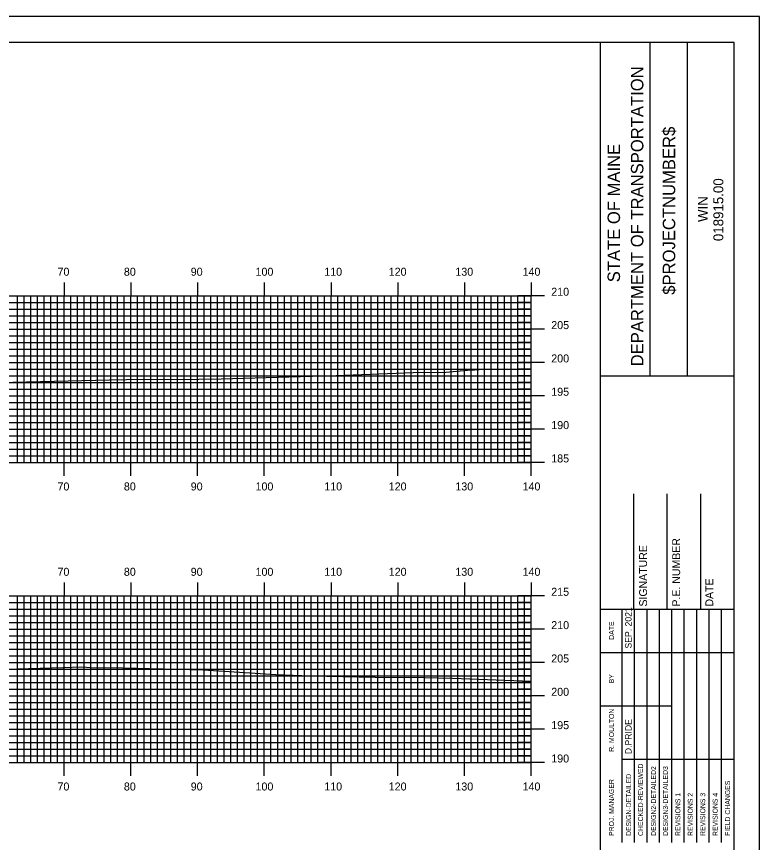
# Model space of a CAD drawing. Extents: x 1821998 to 1822342, y 442591 to 442811.
# Drawn here: x 1822227.1 to 1822338.5, y 442686.7 to 442810.5 of the extents above; entities that cross this region are included whole.
import ezdxf

# ---------------------------------------------------------------- set-up
doc = ezdxf.new("R2010")
doc.units = 0
for name, color, linetype in [('BORDER', 7, 'Continuous'), ('H_V ANNOTATION', 7, 'Continuous'), ('MAJOR', 7, 'Continuous'), ('MINOR', 7, 'Continuous'), ('PLOT BOUNDARY', 7, 'Continuous'), ('S_Roadway_Centerline', 7, 'Continuous')]:
    doc.layers.add(name, color=color, linetype=linetype)

msp = doc.modelspace()

# ---------------------------------------------------------------- linework, layer by layer
at = {"layer": 'BORDER'}
for p, q in [((1822314.66, 442596.67), (1822314.66, 442806.67)), ((1822322.11, 442756.66), (1822322.11, 442806.66)), ((1822327.7, 442756.66), (1822327.7, 442806.66)), ((1822314.66, 442756.65), (1822334.66, 442756.65)), ((1822319.66, 442721.67), (1822319.66, 442738.97)), ((1822324.66, 442721.67), (1822324.66, 442738.97)), ((1822329.66, 442721.67), (1822329.66, 442738.97)), ((1822314.66, 442721.67), (1822334.66, 442721.67))]:
    msp.add_line(p, q, dxfattribs=at)
msp.add_lwpolyline([(1822014.66, 442596.67), (1822334.66, 442596.67), (1822334.66, 442806.67), (1822014.66, 442806.67)], close=True, dxfattribs=at)
for points in [[(1822317.89, 442715.17), (1822317.89, 442721.67)], [(1822319.75, 442686.68), (1822319.75, 442721.67)], [(1822321.61, 442721.67), (1822321.61, 442686.68)], [(1822323.48, 442686.68), (1822323.48, 442721.67)], [(1822325.34, 442686.68), (1822325.34, 442721.67)], [(1822327.2, 442686.68), (1822327.2, 442721.67)], [(1822329.07, 442686.68), (1822329.07, 442721.67)], [(1822330.93, 442686.68), (1822330.93, 442721.67)], [(1822332.79, 442686.68), (1822332.79, 442721.67)], [(1822317.89, 442686.68), (1822317.89, 442720.26)], [(1822314.66, 442715.17), (1822334.66, 442715.17)], [(1822314.66, 442707.17), (1822317.89, 442707.17)], [(1822317.89, 442707.17), (1822325.34, 442707.17)], [(1822317.89, 442699.17), (1822334.66, 442699.17)]]:
    msp.add_lwpolyline(points, dxfattribs=at)
at = {"layer": 'MAJOR'}
for p, q in [((1822234.26, 442770.67), (1822234.26, 442768.67)), ((1822244.26, 442770.67), (1822244.26, 442768.67)), ((1822254.26, 442770.67), (1822254.26, 442768.67)), ((1822264.26, 442770.67), (1822264.26, 442768.67)), ((1822274.26, 442770.67), (1822274.26, 442768.67)), ((1822284.26, 442770.67), (1822284.26, 442768.67)), ((1822294.26, 442770.67), (1822294.26, 442768.67)), ((1822304.26, 442770.67), (1822304.26, 442768.67)), ((1822024.26, 442768.67), (1822304.26, 442768.67)), ((1822024.26, 442768.67), (1822304.26, 442768.67)), ((1822234.26, 442743.67), (1822234.26, 442768.67)), ((1822244.26, 442743.67), (1822244.26, 442768.67)), ((1822254.26, 442743.67), (1822254.26, 442768.67)), ((1822264.26, 442743.67), (1822264.26, 442768.67)), ((1822274.26, 442743.67), (1822274.26, 442768.67)), ((1822284.26, 442743.67), (1822284.26, 442768.67)), ((1822294.26, 442743.67), (1822294.26, 442768.67)), ((1822306.26, 442768.67), (1822302.25, 442768.67)), ((1822304.26, 442743.67), (1822304.26, 442768.67)), ((1822304.26, 442743.67), (1822304.26, 442768.67)), ((1822024.26, 442763.67), (1822304.26, 442763.67)), ((1822306.26, 442763.67), (1822302.25, 442763.67)), ((1822024.26, 442758.67), (1822304.26, 442758.67)), ((1822306.26, 442758.67), (1822302.25, 442758.67)), ((1822024.26, 442753.67), (1822304.26, 442753.67)), ((1822306.26, 442753.67), (1822302.25, 442753.67)), ((1822024.26, 442748.67), (1822304.26, 442748.67)), ((1822306.26, 442748.67), (1822302.25, 442748.67)), ((1822024.26, 442743.67), (1822304.26, 442743.67)), ((1822024.26, 442743.67), (1822304.26, 442743.67)), ((1822234.26, 442741.66), (1822234.26, 442743.67)), ((1822244.26, 442741.66), (1822244.26, 442743.67)), ((1822254.26, 442741.66), (1822254.26, 442743.67)), ((1822264.26, 442741.66), (1822264.26, 442743.67)), ((1822274.26, 442741.66), (1822274.26, 442743.67)), ((1822284.26, 442741.66), (1822284.26, 442743.67)), ((1822294.26, 442741.66), (1822294.26, 442743.67)), ((1822306.26, 442743.67), (1822302.25, 442743.67)), ((1822304.26, 442741.66), (1822304.26, 442743.67)), ((1822234.26, 442725.67), (1822234.26, 442723.67)), ((1822244.26, 442725.67), (1822244.26, 442723.67)), ((1822254.26, 442725.67), (1822254.26, 442723.67)), ((1822264.26, 442725.67), (1822264.26, 442723.67)), ((1822274.26, 442725.67), (1822274.26, 442723.67)), ((1822284.26, 442725.67), (1822284.26, 442723.67)), ((1822294.26, 442725.67), (1822294.26, 442723.67)), ((1822304.26, 442725.67), (1822304.26, 442723.67)), ((1822024.26, 442723.67), (1822304.26, 442723.67)), ((1822024.26, 442723.67), (1822304.26, 442723.67)), ((1822234.26, 442698.67), (1822234.26, 442723.67)), ((1822244.26, 442698.67), (1822244.26, 442723.67)), ((1822254.26, 442698.67), (1822254.26, 442723.67)), ((1822264.26, 442698.67), (1822264.26, 442723.67)), ((1822274.26, 442698.67), (1822274.26, 442723.67)), ((1822284.26, 442698.67), (1822284.26, 442723.67)), ((1822294.26, 442698.67), (1822294.26, 442723.67)), ((1822306.26, 442723.67), (1822302.25, 442723.67)), ((1822304.26, 442698.67), (1822304.26, 442723.67)), ((1822304.26, 442698.67), (1822304.26, 442723.67)), ((1822024.26, 442718.67), (1822304.26, 442718.67)), ((1822306.26, 442718.67), (1822302.25, 442718.67)), ((1822024.26, 442713.67), (1822304.26, 442713.67)), ((1822306.26, 442713.67), (1822302.25, 442713.67)), ((1822024.26, 442708.67), (1822304.26, 442708.67)), ((1822306.26, 442708.67), (1822302.25, 442708.67)), ((1822024.26, 442703.67), (1822304.26, 442703.67)), ((1822306.26, 442703.67), (1822302.25, 442703.67)), ((1822024.26, 442698.67), (1822304.26, 442698.67)), ((1822024.26, 442698.67), (1822304.26, 442698.67)), ((1822234.26, 442696.66), (1822234.26, 442698.67)), ((1822244.26, 442696.66), (1822244.26, 442698.67)), ((1822254.26, 442696.66), (1822254.26, 442698.67)), ((1822264.26, 442696.66), (1822264.26, 442698.67)), ((1822274.26, 442696.66), (1822274.26, 442698.67)), ((1822284.26, 442696.66), (1822284.26, 442698.67)), ((1822294.26, 442696.66), (1822294.26, 442698.67)), ((1822306.26, 442698.67), (1822302.25, 442698.67)), ((1822304.26, 442696.66), (1822304.26, 442698.67))]:
    msp.add_line(p, q, dxfattribs=at)
at = {"layer": 'MINOR'}
for p, q in [((1822227.26, 442743.67), (1822227.26, 442768.67)), ((1822228.26, 442743.67), (1822228.26, 442768.67)), ((1822229.26, 442743.67), (1822229.26, 442768.67)), ((1822230.26, 442743.67), (1822230.26, 442768.67)), ((1822231.26, 442743.67), (1822231.26, 442768.67)), ((1822232.26, 442743.67), (1822232.26, 442768.67)), ((1822233.26, 442743.67), (1822233.26, 442768.67)), ((1822235.26, 442743.67), (1822235.26, 442768.67)), ((1822236.26, 442743.67), (1822236.26, 442768.67)), ((1822237.26, 442743.67), (1822237.26, 442768.67)), ((1822238.26, 442743.67), (1822238.26, 442768.67)), ((1822239.26, 442743.67), (1822239.26, 442768.67)), ((1822240.26, 442743.67), (1822240.26, 442768.67)), ((1822241.26, 442743.67), (1822241.26, 442768.67)), ((1822242.26, 442743.67), (1822242.26, 442768.67)), ((1822243.26, 442743.67), (1822243.26, 442768.67)), ((1822245.26, 442743.67), (1822245.26, 442768.67)), ((1822246.26, 442743.67), (1822246.26, 442768.67)), ((1822247.26, 442743.67), (1822247.26, 442768.67)), ((1822248.26, 442743.67), (1822248.26, 442768.67)), ((1822249.26, 442743.67), (1822249.26, 442768.67)), ((1822250.26, 442743.67), (1822250.26, 442768.67)), ((1822251.26, 442743.67), (1822251.26, 442768.67)), ((1822252.26, 442743.67), (1822252.26, 442768.67)), ((1822253.26, 442743.67), (1822253.26, 442768.67)), ((1822255.26, 442743.67), (1822255.26, 442768.67)), ((1822256.26, 442743.67), (1822256.26, 442768.67)), ((1822257.26, 442743.67), (1822257.26, 442768.67)), ((1822258.26, 442743.67), (1822258.26, 442768.67)), ((1822259.26, 442743.67), (1822259.26, 442768.67)), ((1822260.26, 442743.67), (1822260.26, 442768.67)), ((1822261.26, 442743.67), (1822261.26, 442768.67)), ((1822262.26, 442743.67), (1822262.26, 442768.67)), ((1822263.26, 442743.67), (1822263.26, 442768.67)), ((1822265.26, 442743.67), (1822265.26, 442768.67)), ((1822266.26, 442743.67), (1822266.26, 442768.67)), ((1822267.26, 442743.67), (1822267.26, 442768.67)), ((1822268.26, 442743.67), (1822268.26, 442768.67)), ((1822269.26, 442743.67), (1822269.26, 442768.67)), ((1822270.26, 442743.67), (1822270.26, 442768.67)), ((1822271.26, 442743.67), (1822271.26, 442768.67)), ((1822272.26, 442743.67), (1822272.26, 442768.67)), ((1822273.26, 442743.67), (1822273.26, 442768.67)), ((1822275.26, 442743.67), (1822275.26, 442768.67)), ((1822276.26, 442743.67), (1822276.26, 442768.67)), ((1822277.26, 442743.67), (1822277.26, 442768.67)), ((1822278.26, 442743.67), (1822278.26, 442768.67)), ((1822279.26, 442743.67), (1822279.26, 442768.67)), ((1822280.26, 442743.67), (1822280.26, 442768.67)), ((1822281.26, 442743.67), (1822281.26, 442768.67)), ((1822282.26, 442743.67), (1822282.26, 442768.67)), ((1822283.26, 442743.67), (1822283.26, 442768.67)), ((1822285.26, 442743.67), (1822285.26, 442768.67)), ((1822286.26, 442743.67), (1822286.26, 442768.67)), ((1822287.26, 442743.67), (1822287.26, 442768.67)), ((1822288.26, 442743.67), (1822288.26, 442768.67)), ((1822289.26, 442743.67), (1822289.26, 442768.67)), ((1822290.26, 442743.67), (1822290.26, 442768.67)), ((1822291.26, 442743.67), (1822291.26, 442768.67)), ((1822292.26, 442743.67), (1822292.26, 442768.67)), ((1822293.26, 442743.67), (1822293.26, 442768.67)), ((1822295.26, 442743.67), (1822295.26, 442768.67)), ((1822296.26, 442743.67), (1822296.26, 442768.67)), ((1822297.26, 442743.67), (1822297.26, 442768.67)), ((1822298.26, 442743.67), (1822298.26, 442768.67)), ((1822299.26, 442743.67), (1822299.26, 442768.67)), ((1822300.26, 442743.67), (1822300.26, 442768.67)), ((1822301.26, 442743.67), (1822301.26, 442768.67)), ((1822302.26, 442743.67), (1822302.26, 442768.67)), ((1822303.26, 442743.67), (1822303.26, 442768.67)), ((1822024.26, 442767.67), (1822304.26, 442767.67)), ((1822304.26, 442767.67), (1822302.25, 442767.67)), ((1822024.26, 442766.67), (1822304.26, 442766.67)), ((1822304.26, 442766.67), (1822302.25, 442766.67)), ((1822024.26, 442765.67), (1822304.26, 442765.67)), ((1822304.26, 442765.67), (1822302.25, 442765.67)), ((1822024.26, 442764.67), (1822304.26, 442764.67)), ((1822304.26, 442764.67), (1822302.25, 442764.67)), ((1822024.26, 442762.67), (1822304.26, 442762.67)), ((1822304.26, 442762.67), (1822302.25, 442762.67)), ((1822024.26, 442761.67), (1822304.26, 442761.67)), ((1822304.26, 442761.67), (1822302.25, 442761.67)), ((1822024.26, 442760.67), (1822304.26, 442760.67)), ((1822304.26, 442760.67), (1822302.25, 442760.67)), ((1822024.26, 442759.67), (1822304.26, 442759.67)), ((1822304.26, 442759.67), (1822302.25, 442759.67)), ((1822024.26, 442757.67), (1822304.26, 442757.67)), ((1822304.26, 442757.67), (1822302.25, 442757.67)), ((1822024.26, 442756.67), (1822304.26, 442756.67)), ((1822304.26, 442756.67), (1822302.25, 442756.67)), ((1822024.26, 442755.67), (1822304.26, 442755.67)), ((1822304.26, 442755.67), (1822302.25, 442755.67)), ((1822024.26, 442754.67), (1822304.26, 442754.67)), ((1822304.26, 442754.67), (1822302.25, 442754.67)), ((1822024.26, 442752.67), (1822304.26, 442752.67)), ((1822304.26, 442752.67), (1822302.25, 442752.67)), ((1822024.26, 442751.67), (1822304.26, 442751.67)), ((1822304.26, 442751.67), (1822302.25, 442751.67)), ((1822024.26, 442750.67), (1822304.26, 442750.67)), ((1822304.26, 442750.67), (1822302.25, 442750.67)), ((1822024.26, 442749.67), (1822304.26, 442749.67)), ((1822304.26, 442749.67), (1822302.25, 442749.67)), ((1822024.26, 442747.67), (1822304.26, 442747.67)), ((1822304.26, 442747.67), (1822302.25, 442747.67)), ((1822024.26, 442746.67), (1822304.26, 442746.67)), ((1822304.26, 442746.67), (1822302.25, 442746.67)), ((1822024.26, 442745.67), (1822304.26, 442745.67)), ((1822304.26, 442745.67), (1822302.25, 442745.67)), ((1822024.26, 442744.67), (1822304.26, 442744.67)), ((1822304.26, 442744.67), (1822302.25, 442744.67)), ((1822227.26, 442698.67), (1822227.26, 442723.67)), ((1822228.26, 442698.67), (1822228.26, 442723.67)), ((1822229.26, 442698.67), (1822229.26, 442723.67)), ((1822230.26, 442698.67), (1822230.26, 442723.67)), ((1822231.26, 442698.67), (1822231.26, 442723.67)), ((1822232.26, 442698.67), (1822232.26, 442723.67)), ((1822233.26, 442698.67), (1822233.26, 442723.67)), ((1822235.26, 442698.67), (1822235.26, 442723.67)), ((1822236.26, 442698.67), (1822236.26, 442723.67)), ((1822237.26, 442698.67), (1822237.26, 442723.67)), ((1822238.26, 442698.67), (1822238.26, 442723.67)), ((1822239.26, 442698.67), (1822239.26, 442723.67)), ((1822240.26, 442698.67), (1822240.26, 442723.67)), ((1822241.26, 442698.67), (1822241.26, 442723.67)), ((1822242.26, 442698.67), (1822242.26, 442723.67)), ((1822243.26, 442698.67), (1822243.26, 442723.67)), ((1822245.26, 442698.67), (1822245.26, 442723.67)), ((1822246.26, 442698.67), (1822246.26, 442723.67)), ((1822247.26, 442698.67), (1822247.26, 442723.67)), ((1822248.26, 442698.67), (1822248.26, 442723.67)), ((1822249.26, 442698.67), (1822249.26, 442723.67)), ((1822250.26, 442698.67), (1822250.26, 442723.67)), ((1822251.26, 442698.67), (1822251.26, 442723.67)), ((1822252.26, 442698.67), (1822252.26, 442723.67)), ((1822253.26, 442698.67), (1822253.26, 442723.67)), ((1822255.26, 442698.67), (1822255.26, 442723.67)), ((1822256.26, 442698.67), (1822256.26, 442723.67)), ((1822257.26, 442698.67), (1822257.26, 442723.67)), ((1822258.26, 442698.67), (1822258.26, 442723.67)), ((1822259.26, 442698.67), (1822259.26, 442723.67)), ((1822260.26, 442698.67), (1822260.26, 442723.67)), ((1822261.26, 442698.67), (1822261.26, 442723.67)), ((1822262.26, 442698.67), (1822262.26, 442723.67)), ((1822263.26, 442698.67), (1822263.26, 442723.67)), ((1822265.26, 442698.67), (1822265.26, 442723.67)), ((1822266.26, 442698.67), (1822266.26, 442723.67)), ((1822267.26, 442698.67), (1822267.26, 442723.67)), ((1822268.26, 442698.67), (1822268.26, 442723.67)), ((1822269.26, 442698.67), (1822269.26, 442723.67)), ((1822270.26, 442698.67), (1822270.26, 442723.67)), ((1822271.26, 442698.67), (1822271.26, 442723.67)), ((1822272.26, 442698.67), (1822272.26, 442723.67)), ((1822273.26, 442698.67), (1822273.26, 442723.67)), ((1822275.26, 442698.67), (1822275.26, 442723.67)), ((1822276.26, 442698.67), (1822276.26, 442723.67)), ((1822277.26, 442698.67), (1822277.26, 442723.67)), ((1822278.26, 442698.67), (1822278.26, 442723.67)), ((1822279.26, 442698.67), (1822279.26, 442723.67)), ((1822280.26, 442698.67), (1822280.26, 442723.67)), ((1822281.26, 442698.67), (1822281.26, 442723.67)), ((1822282.26, 442698.67), (1822282.26, 442723.67)), ((1822283.26, 442698.67), (1822283.26, 442723.67)), ((1822285.26, 442698.67), (1822285.26, 442723.67)), ((1822286.26, 442698.67), (1822286.26, 442723.67)), ((1822287.26, 442698.67), (1822287.26, 442723.67)), ((1822288.26, 442698.67), (1822288.26, 442723.67)), ((1822289.26, 442698.67), (1822289.26, 442723.67)), ((1822290.26, 442698.67), (1822290.26, 442723.67)), ((1822291.26, 442698.67), (1822291.26, 442723.67)), ((1822292.26, 442698.67), (1822292.26, 442723.67)), ((1822293.26, 442698.67), (1822293.26, 442723.67)), ((1822295.26, 442698.67), (1822295.26, 442723.67)), ((1822296.26, 442698.67), (1822296.26, 442723.67)), ((1822297.26, 442698.67), (1822297.26, 442723.67)), ((1822298.26, 442698.67), (1822298.26, 442723.67)), ((1822299.26, 442698.67), (1822299.26, 442723.67)), ((1822300.26, 442698.67), (1822300.26, 442723.67)), ((1822301.26, 442698.67), (1822301.26, 442723.67)), ((1822302.26, 442698.67), (1822302.26, 442723.67)), ((1822303.26, 442698.67), (1822303.26, 442723.67)), ((1822024.26, 442722.67), (1822304.26, 442722.67)), ((1822024.26, 442721.67), (1822304.26, 442721.67)), ((1822304.26, 442722.67), (1822302.25, 442722.67)), ((1822304.26, 442721.67), (1822302.25, 442721.67)), ((1822024.26, 442720.67), (1822304.26, 442720.67)), ((1822304.26, 442720.67), (1822302.25, 442720.67)), ((1822024.26, 442719.67), (1822304.26, 442719.67)), ((1822304.26, 442719.67), (1822302.25, 442719.67)), ((1822024.26, 442717.67), (1822304.26, 442717.67)), ((1822024.26, 442716.67), (1822304.26, 442716.67)), ((1822304.26, 442717.67), (1822302.25, 442717.67)), ((1822304.26, 442716.67), (1822302.25, 442716.67)), ((1822024.26, 442715.67), (1822304.26, 442715.67)), ((1822304.26, 442715.67), (1822302.25, 442715.67)), ((1822024.26, 442714.67), (1822304.26, 442714.67)), ((1822304.26, 442714.67), (1822302.25, 442714.67)), ((1822024.26, 442712.67), (1822304.26, 442712.67)), ((1822024.26, 442711.67), (1822304.26, 442711.67)), ((1822304.26, 442712.67), (1822302.25, 442712.67)), ((1822304.26, 442711.67), (1822302.25, 442711.67)), ((1822024.26, 442710.67), (1822304.26, 442710.67)), ((1822304.26, 442710.67), (1822302.25, 442710.67)), ((1822024.26, 442709.67), (1822304.26, 442709.67)), ((1822304.26, 442709.67), (1822302.25, 442709.67)), ((1822024.26, 442707.67), (1822304.26, 442707.67)), ((1822024.26, 442706.67), (1822304.26, 442706.67)), ((1822304.26, 442707.67), (1822302.25, 442707.67)), ((1822304.26, 442706.67), (1822302.25, 442706.67)), ((1822024.26, 442705.67), (1822304.26, 442705.67)), ((1822304.26, 442705.67), (1822302.25, 442705.67)), ((1822024.26, 442704.67), (1822304.26, 442704.67)), ((1822304.26, 442704.67), (1822302.25, 442704.67)), ((1822024.26, 442702.67), (1822304.26, 442702.67)), ((1822024.26, 442701.67), (1822304.26, 442701.67)), ((1822304.26, 442702.67), (1822302.25, 442702.67)), ((1822304.26, 442701.67), (1822302.25, 442701.67)), ((1822024.26, 442700.67), (1822304.26, 442700.67)), ((1822304.26, 442700.67), (1822302.25, 442700.67)), ((1822024.26, 442699.67), (1822304.26, 442699.67)), ((1822304.26, 442699.67), (1822302.25, 442699.67))]:
    msp.add_line(p, q, dxfattribs=at)
at = {"layer": 'PLOT BOUNDARY'}
msp.add_lwpolyline([(1821998.47, 442590.55), (1822338.47, 442590.55), (1822338.47, 442810.55), (1821998.47, 442810.55)], close=True, dxfattribs=at)
at = {"layer": 'S_Roadway_Centerline'}
for points in [[(1822226.56, 442755.71), (1822241.04, 442756.07), (1822243.62, 442756.09), (1822254.43, 442756.18), (1822257.79, 442756.21), (1822267.95, 442756.52), (1822275.03, 442756.72), (1822286.57, 442757.15), (1822291.48, 442757.23), (1822294.7, 442757.52), (1822295.74, 442757.56), (1822297.18, 442757.64), (1822304.26, 442757.64)], [(1822220.15, 442712.54), (1822234.11, 442712.9), (1822236.86, 442713.02), (1822238.33, 442712.94), (1822243.05, 442712.87), (1822255.1, 442712.55), (1822265.97, 442711.89), (1822271.2, 442711.66), (1822280.89, 442711.45), (1822288.2, 442711.41), (1822292.46, 442711.31), (1822304.26, 442710.85)]]:
    msp.add_lwpolyline(points, dxfattribs=at)

# ---------------------------------------------------------------- texts
at = {"layer": 'BORDER'}
for s, height, p in [('DEPARTMENT OF TRANSPORTATION', 1.8635, (1822321.07, 442758.08)), ('$PROJECTNUMBER$', 1.8635, (1822325.84, 442768.82)), ('STATE OF MAINE', 1.8635, (1822317.57, 442770.69)), ('018915.00', 1.491, (1822333.05, 442776.86)), ('WIN', 1.491, (1822330.73, 442779.73)), ('P.E. NUMBER', 1.1811, (1822326.58, 442722.06)), ('SIGNATURE', 1.181, (1822321.62, 442722.06)), ('DATE', 1.181, (1822331.54, 442722.06)), ('SEP. 2021', 0.969, (1822319.3, 442715.76)), ('DATE', 0.743, (1822316.66, 442717.08)), ('BY', 0.743, (1822316.66, 442710.54)), ('R. MOULTON', 0.745, (1822316.67, 442700.28)), ('D.PRIDE', 0.969, (1822319.3, 442699.92)), ('CHECKED-REVIEWED', 0.7455, (1822321.02, 442687.65)), ('DESIGN2-DETAILED2', 0.7455, (1822322.96, 442687.65)), ('DESIGN3-DETAILED3', 0.7455, (1822324.75, 442687.65)), ('PROJ. MANAGER', 0.7455, (1822316.66, 442687.65)), ('DESIGN-DETAILED', 0.7455, (1822319.23, 442687.65)), ('FIELD CHANGES', 0.7455, (1822334.06, 442687.65)), ('REVISIONS 1', 0.7455, (1822326.61, 442687.65)), ('REVISIONS 2', 0.7455, (1822328.47, 442687.65)), ('REVISIONS 3', 0.7455, (1822330.34, 442687.65)), ('REVISIONS 4', 0.7455, (1822332.2, 442687.65))]:
    msp.add_text(s, height=height, rotation=90, dxfattribs=at).set_placement(p)
at = {"layer": 'H_V ANNOTATION'}
for s, p in [('70', (1822233.26, 442771.67)), ('80', (1822243.21, 442771.67)), ('90', (1822253.23, 442771.67)), ('100', (1822262.94, 442771.67)), ('110', (1822273.24, 442771.67)), ('120', (1822282.9, 442771.67)), ('130', (1822292.89, 442771.67)), ('140', (1822302.96, 442771.67)), ('210', (1822307.26, 442768.67)), ('205', (1822307.26, 442763.67)), ('200', (1822307.26, 442758.67)), ('195', (1822307.26, 442753.67)), ('190', (1822307.26, 442748.67)), ('185', (1822307.26, 442743.67)), ('70', (1822233.26, 442739.47)), ('80', (1822243.21, 442739.47)), ('90', (1822253.23, 442739.47)), ('100', (1822262.94, 442739.47)), ('110', (1822273.24, 442739.47)), ('120', (1822282.9, 442739.47)), ('130', (1822292.89, 442739.47)), ('140', (1822302.96, 442739.47)), ('70', (1822233.26, 442726.67)), ('80', (1822243.21, 442726.67)), ('90', (1822253.23, 442726.67)), ('100', (1822262.94, 442726.67)), ('110', (1822273.24, 442726.67)), ('120', (1822282.9, 442726.67)), ('130', (1822292.89, 442726.67)), ('140', (1822302.96, 442726.67)), ('215', (1822307.26, 442723.67)), ('210', (1822307.26, 442718.67)), ('205', (1822307.26, 442713.67)), ('200', (1822307.26, 442708.67)), ('195', (1822307.26, 442703.67)), ('190', (1822307.26, 442698.67)), ('70', (1822233.26, 442694.47)), ('80', (1822243.21, 442694.47)), ('90', (1822253.23, 442694.47)), ('100', (1822262.94, 442694.47)), ('110', (1822273.24, 442694.47)), ('120', (1822282.9, 442694.47)), ('130', (1822292.89, 442694.47)), ('140', (1822302.96, 442694.47))]:
    msp.add_text(s, height=1.2, dxfattribs=at).set_placement(p)

doc.saveas('drawing.dxf')
